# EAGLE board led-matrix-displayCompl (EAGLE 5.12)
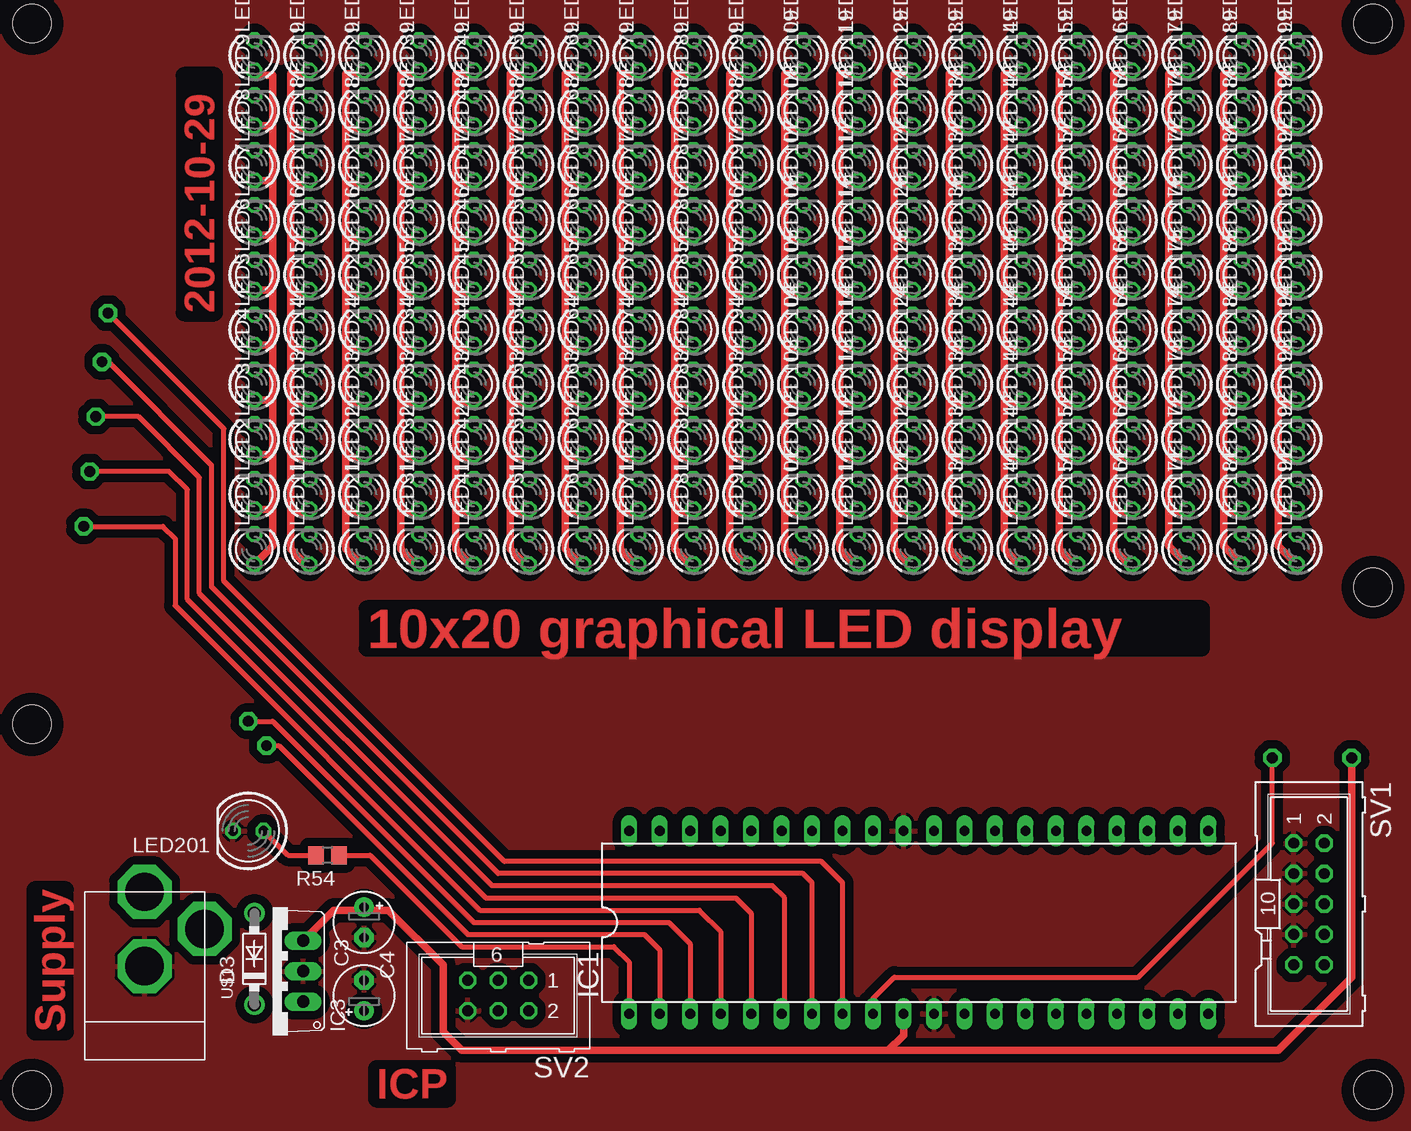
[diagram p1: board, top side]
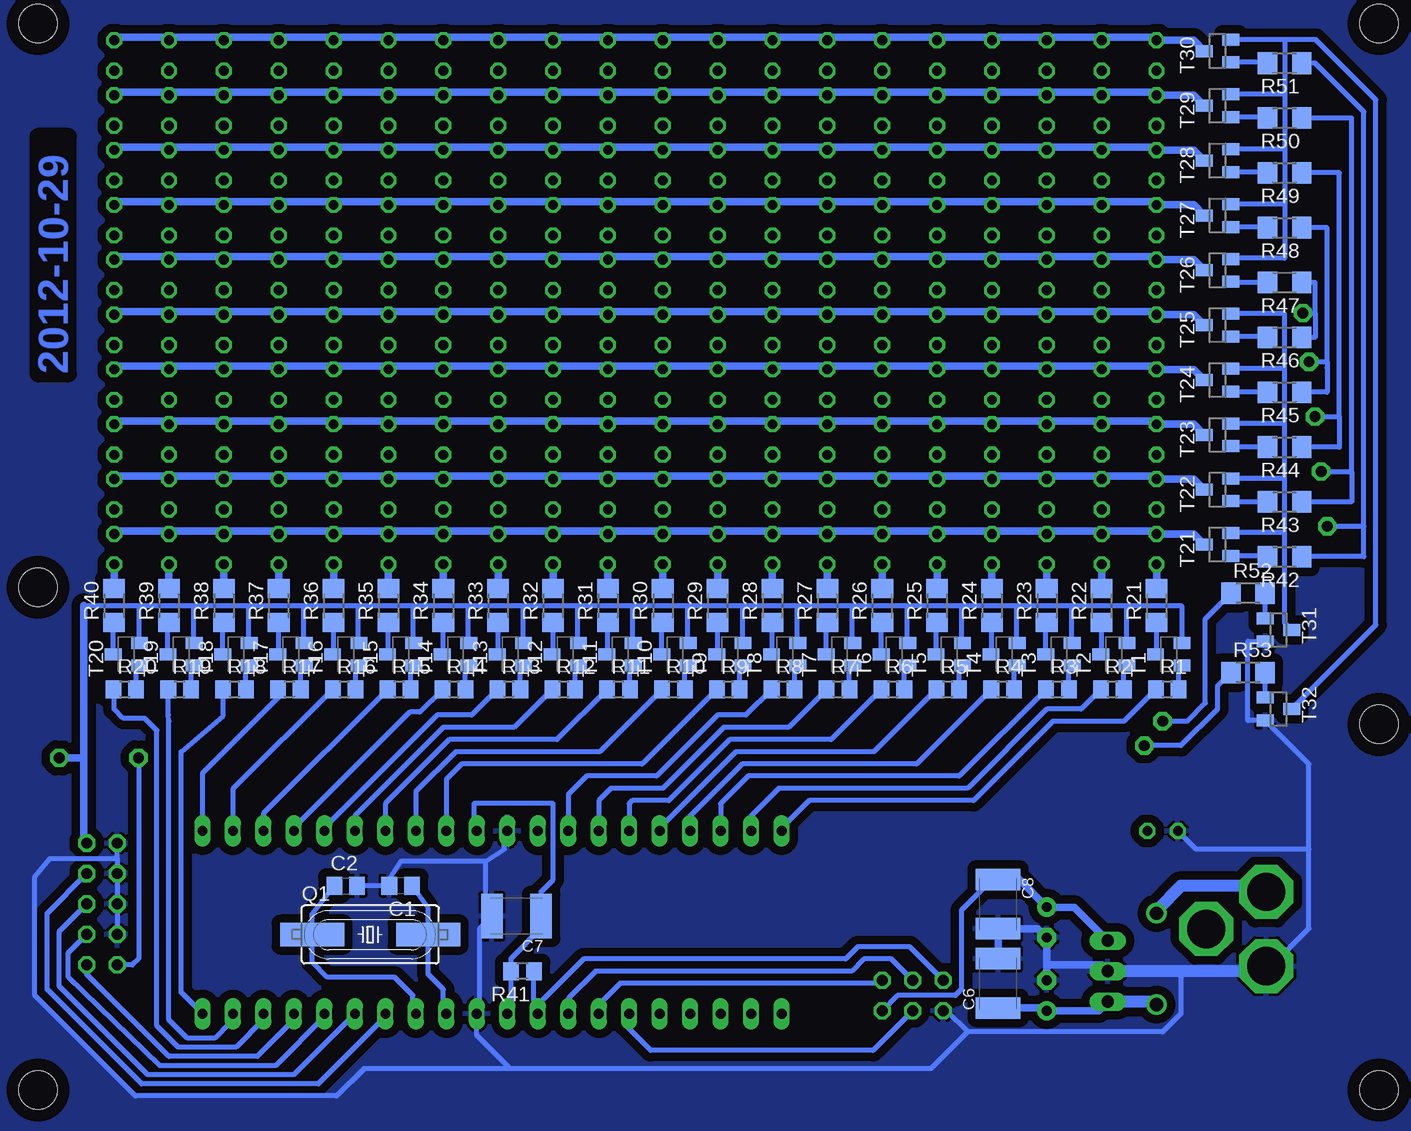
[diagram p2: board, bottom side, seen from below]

No outline drawn. Coordinates in mm, seen from the top.
Copper layers (1*16): Top 0.035mm / dielectric 1.5mm / Bottom 0.035mm
Design rules "default *": minimum track width 16mil, minimum drill 24mil, track to track 12mil, track to pad 12mil, pad to pad 12mil, via to via 8mil, smd to smd 8mil, copper to edge 40mil, drill to drill 8mil, minimum pad ring 10mil, minimum via ring 8mil, stop-mask expansion 4mil, vias tented up to drill 0mil, thermal gap 10mil
Holes 3.2 mm at 105.41,-6.35 105.41,82.55 -6.35,82.55 -6.35,24.13 -6.35,-6.35 105.41,35.56

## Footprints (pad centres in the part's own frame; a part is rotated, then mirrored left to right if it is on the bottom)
C0805 = smd 1.3 x 1.5: 1 -0.95,0; 2 0.95,0
E2,5-5 = drill 0.813 pad 1.6 round: + -1.27,0 | drill 0.813 pad 1.6 octagon: - 1.27,0
C1812K = smd 1.8 x 3.7: 1 -2.05,0; 2 2.05,0
DO41-7.6 = drill 1.1 pad 1.7 round: A 3.81,0; C -3.81,0
DIL40 = drill 0.813 long: 1 -24.13,-7.62; 2 -21.59,-7.62; 3 -19.05,-7.62; 4 -16.51,-7.62; 5 -13.97,-7.62; 6 -11.43,-7.62; 7 -8.89,-7.62; 8 -6.35,-7.62; 9 -3.81,-7.62; 10 -1.27,-7.62; 11 1.27,-7.62; 12 3.81,-7.62; 13 6.35,-7.62; 14 8.89,-7.62; 15 11.43,-7.62; 16 13.97,-7.62; 17 16.51,-7.62; 18 19.05,-7.62; 19 21.59,-7.62; 20 24.13,-7.62; 21 24.13,7.62; 22 21.59,7.62; 23 19.05,7.62; 24 16.51,7.62; 25 13.97,7.62; 26 11.43,7.62; 27 8.89,7.62; 28 6.35,7.62; 29 3.81,7.62; 30 1.27,7.62; 31 -1.27,7.62; 32 -3.81,7.62; 33 -6.35,7.62; 34 -8.89,7.62; 35 -11.43,7.62; 36 -13.97,7.62; 37 -16.51,7.62; 38 -19.05,7.62; 39 -21.59,7.62; 40 -24.13,7.62
TO220V = drill 1.016 long: 1 -2.54,-2.54; 2 0,-2.54; 3 2.54,-2.54
LED3MM = drill 0.813 octagon: A -1.27,0; K 1.27,0
LED5MM = drill 0.813 octagon: A -1.27,0; K 1.27,0
HC49UP = smd 5.334 x 1.93: 1 -4.826,0; 2 4.826,0
R0805 = smd 1.3 x 1.5: 1 -0.95,0; 2 0.95,0
R1206 = smd 1.6 x 1.803: 1 -1.422,0; 2 1.422,0
ML10 = drill 0.914 octagon: 1 -5.08,-1.27; 2 -5.08,1.27; 3 -2.54,-1.27; 4 -2.54,1.27; 5 0,-1.27; 6 0,1.27; 7 2.54,-1.27; 8 2.54,1.27; 9 5.08,-1.27; 10 5.08,1.27
ML6 = drill 0.914 octagon: 1 -2.54,-1.27; 2 -2.54,1.27; 3 0,-1.27; 4 0,1.27; 5 2.54,-1.27; 6 2.54,1.27
SOT23-BEC = smd 1 x 1.4: B -0.95,-1.1; C 0,1.1; E 0.95,-1.1
SOT23 = smd 1 x 1.4: 1 -0.95,-1.1; 2 0.95,-1.1; 3 0,1.1
HOHLBUCHSE = drill 3.2 pad 4.5 octagon: I 0,0; O 6.2,0; O2 3.1,5

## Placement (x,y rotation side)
C1  [C0805]  75.18,10.67 180 bottom
C2  [C0805]  79.76,10.67 0 bottom
C3  [E2,5-5]  21.34,1.52 90 top
C4  [E2,5-5]  21.34,7.62 270 top
C6  [C1812K]  25.4,2.54 90 bottom
C7  [C1812K]  65.53,8.13 180 bottom
C8  [C1812K]  25.4,9.14 270 bottom
D3  1N5817-B  [DO41-7.6]  12.19,4.57 90 top
IC1  MEGA32-P  [DIL40]  67.56,7.62 0 top
IC3  7805TV  [TO220V]  13.72,3.56 90 top
LED1  [LED3MM]  12.19,38.73 90 top
LED2  [LED3MM]  12.19,43.31 90 top
LED3  [LED3MM]  12.19,47.88 90 top
LED4  [LED3MM]  12.19,52.45 90 top
LED5  [LED3MM]  12.19,57.02 90 top
LED6  [LED3MM]  12.19,61.59 90 top
LED7  [LED3MM]  12.19,66.17 90 top
LED8  [LED3MM]  12.19,70.74 90 top
LED9  [LED3MM]  12.19,75.31 90 top
LED10  [LED3MM]  12.19,79.88 90 top
LED11  [LED3MM]  16.76,38.73 90 top
LED12  [LED3MM]  16.76,43.31 90 top
LED13  [LED3MM]  16.76,47.88 90 top
LED14  [LED3MM]  16.76,52.45 90 top
LED15  [LED3MM]  16.76,57.02 90 top
LED16  [LED3MM]  16.76,61.59 90 top
LED17  [LED3MM]  16.76,66.17 90 top
LED18  [LED3MM]  16.76,70.74 90 top
LED19  [LED3MM]  16.76,75.31 90 top
LED20  [LED3MM]  16.76,79.88 90 top
LED21  [LED3MM]  21.34,38.73 90 top
LED22  [LED3MM]  21.34,43.31 90 top
LED23  [LED3MM]  21.34,47.88 90 top
LED24  [LED3MM]  21.34,52.45 90 top
LED25  [LED3MM]  21.34,57.02 90 top
LED26  [LED3MM]  21.34,61.59 90 top
LED27  [LED3MM]  21.34,66.17 90 top
LED28  [LED3MM]  21.34,70.74 90 top
LED29  [LED3MM]  21.34,75.31 90 top
LED30  [LED3MM]  21.34,79.88 90 top
LED31  [LED3MM]  25.91,38.73 90 top
LED32  [LED3MM]  25.91,43.31 90 top
LED33  [LED3MM]  25.91,47.88 90 top
LED34  [LED3MM]  25.91,52.45 90 top
LED35  [LED3MM]  25.91,57.02 90 top
LED36  [LED3MM]  25.91,61.59 90 top
LED37  [LED3MM]  25.91,66.17 90 top
LED38  [LED3MM]  25.91,70.74 90 top
LED39  [LED3MM]  25.91,75.31 90 top
LED40  [LED3MM]  25.91,79.88 90 top
LED41  [LED3MM]  30.48,38.73 90 top
LED42  [LED3MM]  30.48,43.31 90 top
LED43  [LED3MM]  30.48,47.88 90 top
LED44  [LED3MM]  30.48,52.45 90 top
LED45  [LED3MM]  30.48,57.02 90 top
LED46  [LED3MM]  30.48,61.59 90 top
LED47  [LED3MM]  30.48,66.17 90 top
LED48  [LED3MM]  30.48,70.74 90 top
LED49  [LED3MM]  30.48,75.31 90 top
LED50  [LED3MM]  30.48,79.88 90 top
LED51  [LED3MM]  35.05,38.73 90 top
LED52  [LED3MM]  35.05,43.31 90 top
LED53  [LED3MM]  35.05,47.88 90 top
LED54  [LED3MM]  35.05,52.45 90 top
LED55  [LED3MM]  35.05,57.02 90 top
LED56  [LED3MM]  35.05,61.59 90 top
LED57  [LED3MM]  35.05,66.17 90 top
LED58  [LED3MM]  35.05,70.74 90 top
LED59  [LED3MM]  35.05,75.31 90 top
LED60  [LED3MM]  35.05,79.88 90 top
LED61  [LED3MM]  39.62,38.73 90 top
LED62  [LED3MM]  39.62,43.31 90 top
LED63  [LED3MM]  39.62,47.88 90 top
LED64  [LED3MM]  39.62,52.45 90 top
LED65  [LED3MM]  39.62,57.02 90 top
LED66  [LED3MM]  39.62,61.59 90 top
LED67  [LED3MM]  39.62,66.17 90 top
LED68  [LED3MM]  39.62,70.74 90 top
LED69  [LED3MM]  39.62,75.31 90 top
LED70  [LED3MM]  39.62,79.88 90 top
LED71  [LED3MM]  44.2,38.73 90 top
LED72  [LED3MM]  44.2,43.31 90 top
LED73  [LED3MM]  44.2,47.88 90 top
LED74  [LED3MM]  44.2,52.45 90 top
LED75  [LED3MM]  44.2,57.02 90 top
LED76  [LED3MM]  44.2,61.59 90 top
LED77  [LED3MM]  44.2,66.17 90 top
LED78  [LED3MM]  44.2,70.74 90 top
LED79  [LED3MM]  44.2,75.31 90 top
LED80  [LED3MM]  44.2,79.88 90 top
LED81  [LED3MM]  48.77,38.73 90 top
LED82  [LED3MM]  48.77,43.31 90 top
LED83  [LED3MM]  48.77,47.88 90 top
LED84  [LED3MM]  48.77,52.45 90 top
LED85  [LED3MM]  48.77,57.02 90 top
LED86  [LED3MM]  48.77,61.59 90 top
LED87  [LED3MM]  48.77,66.17 90 top
LED88  [LED3MM]  48.77,70.74 90 top
LED89  [LED3MM]  48.77,75.31 90 top
LED90  [LED3MM]  48.77,79.88 90 top
LED91  [LED3MM]  53.34,38.73 90 top
LED92  [LED3MM]  53.34,43.31 90 top
LED93  [LED3MM]  53.34,47.88 90 top
LED94  [LED3MM]  53.34,52.45 90 top
LED95  [LED3MM]  53.34,57.02 90 top
LED96  [LED3MM]  53.34,61.59 90 top
LED97  [LED3MM]  53.34,66.17 90 top
LED98  [LED3MM]  53.34,70.74 90 top
LED99  [LED3MM]  53.34,75.31 90 top
LED100  [LED3MM]  53.34,79.88 90 top
LED101  [LED3MM]  57.91,38.73 90 top
LED102  [LED3MM]  57.91,43.31 90 top
LED103  [LED3MM]  57.91,47.88 90 top
LED104  [LED3MM]  57.91,52.45 90 top
LED105  [LED3MM]  57.91,57.02 90 top
LED106  [LED3MM]  57.91,61.59 90 top
LED107  [LED3MM]  57.91,66.17 90 top
LED108  [LED3MM]  57.91,70.74 90 top
LED109  [LED3MM]  57.91,75.31 90 top
LED110  [LED3MM]  57.91,79.88 90 top
LED111  [LED3MM]  62.48,38.73 90 top
LED112  [LED3MM]  62.48,43.31 90 top
LED113  [LED3MM]  62.48,47.88 90 top
LED114  [LED3MM]  62.48,52.45 90 top
LED115  [LED3MM]  62.48,57.02 90 top
LED116  [LED3MM]  62.48,61.59 90 top
LED117  [LED3MM]  62.48,66.17 90 top
LED118  [LED3MM]  62.48,70.74 90 top
LED119  [LED3MM]  62.48,75.31 90 top
LED120  [LED3MM]  62.48,79.88 90 top
LED121  [LED3MM]  67.06,38.73 90 top
LED122  [LED3MM]  67.06,43.31 90 top
LED123  [LED3MM]  67.06,47.88 90 top
LED124  [LED3MM]  67.06,52.45 90 top
LED125  [LED3MM]  67.06,57.02 90 top
LED126  [LED3MM]  67.06,61.59 90 top
LED127  [LED3MM]  67.06,66.17 90 top
LED128  [LED3MM]  67.06,70.74 90 top
LED129  [LED3MM]  67.06,75.31 90 top
LED130  [LED3MM]  67.06,79.88 90 top
LED131  [LED3MM]  71.63,38.73 90 top
LED132  [LED3MM]  71.63,43.31 90 top
LED133  [LED3MM]  71.63,47.88 90 top
LED134  [LED3MM]  71.63,52.45 90 top
LED135  [LED3MM]  71.63,57.02 90 top
LED136  [LED3MM]  71.63,61.59 90 top
LED137  [LED3MM]  71.63,66.17 90 top
LED138  [LED3MM]  71.63,70.74 90 top
LED139  [LED3MM]  71.63,75.31 90 top
LED140  [LED3MM]  71.63,79.88 90 top
LED141  [LED3MM]  76.2,38.73 90 top
LED142  [LED3MM]  76.2,43.31 90 top
LED143  [LED3MM]  76.2,47.88 90 top
LED144  [LED3MM]  76.2,52.45 90 top
LED145  [LED3MM]  76.2,57.02 90 top
LED146  [LED3MM]  76.2,61.59 90 top
LED147  [LED3MM]  76.2,66.17 90 top
LED148  [LED3MM]  76.2,70.74 90 top
LED149  [LED3MM]  76.2,75.31 90 top
LED150  [LED3MM]  76.2,79.88 90 top
LED151  [LED3MM]  80.77,38.73 90 top
LED152  [LED3MM]  80.77,43.31 90 top
LED153  [LED3MM]  80.77,47.88 90 top
LED154  [LED3MM]  80.77,52.45 90 top
LED155  [LED3MM]  80.77,57.02 90 top
LED156  [LED3MM]  80.77,61.59 90 top
LED157  [LED3MM]  80.77,66.17 90 top
LED158  [LED3MM]  80.77,70.74 90 top
LED159  [LED3MM]  80.77,75.31 90 top
LED160  [LED3MM]  80.77,79.88 90 top
LED161  [LED3MM]  85.34,38.73 90 top
LED162  [LED3MM]  85.34,43.31 90 top
LED163  [LED3MM]  85.34,47.88 90 top
LED164  [LED3MM]  85.34,52.45 90 top
LED165  [LED3MM]  85.34,57.02 90 top
LED166  [LED3MM]  85.34,61.59 90 top
LED167  [LED3MM]  85.34,66.17 90 top
LED168  [LED3MM]  85.34,70.74 90 top
LED169  [LED3MM]  85.34,75.31 90 top
LED170  [LED3MM]  85.34,79.88 90 top
LED171  [LED3MM]  89.92,38.73 90 top
LED172  [LED3MM]  89.92,43.31 90 top
LED173  [LED3MM]  89.92,47.88 90 top
LED174  [LED3MM]  89.92,52.45 90 top
LED175  [LED3MM]  89.92,57.02 90 top
LED176  [LED3MM]  89.92,61.59 90 top
LED177  [LED3MM]  89.92,66.17 90 top
LED178  [LED3MM]  89.92,70.74 90 top
LED179  [LED3MM]  89.92,75.31 90 top
LED180  [LED3MM]  89.92,79.88 90 top
LED181  [LED3MM]  94.49,38.73 90 top
LED182  [LED3MM]  94.49,43.31 90 top
LED183  [LED3MM]  94.49,47.88 90 top
LED184  [LED3MM]  94.49,52.45 90 top
LED185  [LED3MM]  94.49,57.02 90 top
LED186  [LED3MM]  94.49,61.59 90 top
LED187  [LED3MM]  94.49,66.17 90 top
LED188  [LED3MM]  94.49,70.74 90 top
LED189  [LED3MM]  94.49,75.31 90 top
LED190  [LED3MM]  94.49,79.88 90 top
LED191  [LED3MM]  99.06,38.73 90 top
LED192  [LED3MM]  99.06,43.31 90 top
LED193  [LED3MM]  99.06,47.88 90 top
LED194  [LED3MM]  99.06,52.45 90 top
LED195  [LED3MM]  99.06,57.02 90 top
LED196  [LED3MM]  99.06,61.59 90 top
LED197  [LED3MM]  99.06,66.17 90 top
LED198  [LED3MM]  99.06,70.74 90 top
LED199  [LED3MM]  99.06,75.31 90 top
LED200  [LED3MM]  99.06,79.88 90 top
LED201  [LED5MM]  11.68,15.24 180 top
Q1  [HC49UP]  77.72,6.6 0 bottom
R1  10k  [R0805]  11.3,27.05 0 bottom
R2  10k  [R0805]  15.88,27.05 0 bottom
R3  10k  [R0805]  20.45,27.05 0 bottom
R4  10k  [R0805]  25.02,27.05 0 bottom
R5  10k  [R0805]  29.59,27.05 0 bottom
R6  10k  [R0805]  34.16,27.05 0 bottom
R7  10k  [R0805]  38.73,27.05 0 bottom
R8  10k  [R0805]  43.31,27.05 0 bottom
R9  10k  [R0805]  47.88,27.05 0 bottom
R10  10k  [R0805]  52.45,27.05 0 bottom
R11  10k  [R0805]  57.02,27.05 0 bottom
R12  10k  [R0805]  61.59,27.05 0 bottom
R13  10k  [R0805]  66.17,27.05 0 bottom
R14  10k  [R0805]  70.74,27.05 0 bottom
R15  10k  [R0805]  75.31,27.05 0 bottom
R16  10k  [R0805]  79.88,27.05 0 bottom
R17  10k  [R0805]  84.45,27.05 0 bottom
R18  10k  [R0805]  89.03,27.05 0 bottom
R19  10k  [R0805]  93.6,27.05 0 bottom
R20  10k  [R0805]  98.17,27.05 0 bottom
R21  [R1206]  12.19,34.04 90 bottom
R22  [R1206]  16.76,34.04 90 bottom
R23  [R1206]  21.34,34.04 90 bottom
R24  [R1206]  25.91,34.04 90 bottom
R25  [R1206]  30.48,34.04 90 bottom
R26  [R1206]  35.05,34.04 90 bottom
R27  [R1206]  39.62,34.04 90 bottom
R28  [R1206]  44.2,34.04 90 bottom
R29  [R1206]  48.77,34.04 90 bottom
R30  [R1206]  53.34,34.04 90 bottom
R31  [R1206]  57.91,34.04 90 bottom
R32  [R1206]  62.48,34.04 90 bottom
R33  [R1206]  67.06,34.04 90 bottom
R34  [R1206]  71.63,34.04 90 bottom
R35  [R1206]  76.2,34.04 90 bottom
R36  [R1206]  80.77,34.04 90 bottom
R37  [R1206]  85.34,34.04 90 bottom
R38  [R1206]  89.92,34.04 90 bottom
R39  [R1206]  94.49,34.04 90 bottom
R40  [R1206]  99.06,34.04 90 bottom
R41  [R0805]  65.02,3.56 180 bottom
R42  4k7  [R1206]  1.52,38.1 180 bottom
R43  4k7  [R1206]  1.52,42.67 180 bottom
R44  4k7  [R1206]  1.52,47.24 180 bottom
R45  4k7  [R1206]  1.52,51.82 180 bottom
R46  4k7  [R1206]  1.52,56.39 180 bottom
R47  4k7  [R1206]  1.52,60.96 180 bottom
R48  4k7  [R1206]  1.52,65.53 180 bottom
R49  4k7  [R1206]  1.52,70.1 180 bottom
R50  4k7  [R1206]  1.52,74.68 180 bottom
R51  4k7  [R1206]  1.52,79.25 180 bottom
R52  4k7  [R1206]  4.57,35.05 0 bottom
R53  4k7  [R1206]  4.57,28.45 0 bottom
R54  [R0805]  18.29,13.21 180 top
SV1  [ML10]  100.08,9.14 270 top
SV2  [ML6]  32.51,1.52 180 top
T1  [SOT23-BEC]  11.18,29.97 90 bottom
T2  [SOT23-BEC]  15.75,29.97 90 bottom
T3  [SOT23-BEC]  20.32,29.97 90 bottom
T4  [SOT23-BEC]  24.89,29.97 90 bottom
T5  [SOT23-BEC]  29.46,29.97 90 bottom
T6  [SOT23-BEC]  34.04,29.97 90 bottom
T7  [SOT23-BEC]  38.61,29.97 90 bottom
T8  [SOT23-BEC]  43.18,29.97 90 bottom
T9  [SOT23-BEC]  47.75,29.97 90 bottom
T10  [SOT23-BEC]  52.32,29.97 90 bottom
T11  [SOT23-BEC]  56.9,29.97 90 bottom
T12  [SOT23-BEC]  61.47,29.97 90 bottom
T13  [SOT23-BEC]  66.04,29.97 90 bottom
T14  [SOT23-BEC]  70.61,29.97 90 bottom
T15  [SOT23-BEC]  75.18,29.97 90 bottom
T16  [SOT23-BEC]  79.76,29.97 90 bottom
T17  [SOT23-BEC]  84.33,29.97 90 bottom
T18  [SOT23-BEC]  88.9,29.97 90 bottom
T19  [SOT23-BEC]  93.47,29.97 90 bottom
T20  [SOT23-BEC]  98.04,29.97 90 bottom
T21  BC818  [SOT23]  7.11,39.12 90 bottom
T22  BC818  [SOT23]  7.11,43.69 90 bottom
T23  BC818  [SOT23]  7.11,48.26 90 bottom
T24  BC818  [SOT23]  7.11,52.83 90 bottom
T25  BC818  [SOT23]  7.11,57.4 90 bottom
T26  BC818  [SOT23]  7.11,61.98 90 bottom
T27  BC818  [SOT23]  7.11,66.55 90 bottom
T28  BC818  [SOT23]  7.11,71.12 90 bottom
T29  BC818  [SOT23]  7.11,75.69 90 bottom
T30  BC818  [SOT23]  7.11,80.26 90 bottom
T31  BC818  [SOT23]  2.03,32 270 bottom
T32  BC818  [SOT23]  2.03,25.4 270 bottom
U$1  HOHLBUCHSE  [HOHLBUCHSE]  3.05,10.16 270 top

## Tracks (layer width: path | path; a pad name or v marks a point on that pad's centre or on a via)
+5V  (via drill 0.9 pad 1.52)
  Top 0.61: IC3.3 18.8,8.64 23.37,8.64 27.94,4.06 27.94,-1.52 29.46,-3.05 65.02,-3.05 | 65.02,-3.05 66.29,-1.78 IC1.10 | 65.02,-3.05 97.54,-3.05 103.63,3.05 v103.63,21.34
  Bottom 0.406: IC1.10 65.97,0.32 R41.2 65.97,4.62 63.5,7.11 63.5,8.13 C7.1 63.48,10.18 62.48,11.18 62.48,17.53 69.09,17.53 69.09,15.49 IC1.30 | 101.6,14.48 SV1.2 | 14.73,34.04 10.16,34.04 10.08,33.95 T1.E | 19.3,34.04 14.73,34.04 | 23.88,34.04 19.3,34.04 | 28.45,34.04 23.88,34.04 | 33.02,34.04 28.45,34.04 | 37.59,34.04 33.02,34.04 | 42.16,34.04 37.59,34.04 | 46.74,34.04 42.16,34.04 | 51.31,34.04 46.74,34.04 | 55.88,34.04 51.31,34.04 | 60.45,34.04 55.88,34.04 | 65.02,34.04 60.45,34.04 | 69.6,34.04 65.02,34.04 | 74.17,34.04 69.6,34.04 | 78.74,34.04 74.17,34.04 | 83.31,34.04 78.74,34.04 | 87.88,34.04 83.31,34.04 | 92.46,34.04 87.88,34.04 | 97.03,34.04 92.46,34.04 | 101.6,34.04 97.03,34.04 | T2.E 14.73,31.01 14.73,34.04 | T3.E 19.3,31.01 19.3,34.04 | T4.E 23.88,31.01 23.88,34.04 | T5.E 28.45,31.01 28.45,34.04 | T6.E 33.02,31.01 33.02,34.04 | T7.E 37.59,31.01 37.59,34.04 | T8.E 42.16,31.01 42.16,34.04 | T9.E 46.74,31.01 46.74,34.04 | T10.E 51.31,31.01 51.31,34.04 | T12.E 60.45,31.01 60.45,34.04 | T11.E 55.88,31.01 55.88,34.04 | T13.E 65.02,31.01 65.02,34.04 | T14.E 69.6,31.01 69.6,34.04 | T15.E 74.17,31.01 74.17,34.04 | T16.E 78.74,31.01 78.74,34.04 | T17.E 83.31,31.01 83.31,34.04 | T18.E 87.88,31.01 87.88,34.04 | T19.E 92.46,31.01 92.46,34.04 | T20.E 97.03,31.01 97.03,34.04 | SV2.2 33.78,1.52 28.96,1.52 28.45,2.03 28.45,8.64 25.89,11.19 C8.1
  Bottom 0.61: IC3.3 19.05,8.89 C4.+ 23.64,11.19 C8.1 | 101.6,21.34 101.6,34.04 | 101.6,21.34 101.6,14.48 | v103.63,21.34 101.6,21.34
GND
  Bottom 0.406: C2.2 C1.2 76.13,11.24 75.18,12.7 68.07,12.7 | IC1.31 66.55,14.99 66.55,13.72 68.07,12.7 | 68.07,12.7 68.07,8.62 C7.2 67.58,8.11 68.58,7.11 68.58,0.25 IC1.11 68.83,-1.78 66.04,-4.57 | SV1.7 SV1.5 SV1.3 98.81,12.94 | 98.81,12.94 SV1.1 | 9.65,3.56 10.16,3.05 10.16,0 11.68,-1.52 27.94,-1.52 | 27.94,-1.52 29.72,0.25 SV2.6 | T31.2 4.57,31.05 4.57,24.45 T32.2 -0.51,20.81 -0.51,13.72 | -0.51,13.72 -0.51,7.11 2.64,3.96 U$1.O | LED201.K 8.89,13.72 -0.51,13.72 | 27.94,-1.52 30.99,-4.57 66.04,-4.57 | 98.81,12.94 98.83,12.95 104.39,12.95 105.66,11.43 105.66,1.52 97.28,-6.86 80.52,-6.86 78.23,-4.57 66.04,-4.57
  Bottom 0.61: C6.2 C8.2 22.08,7.09 C4.- 21.34,4.06 | 21.34,4.06 C3.- | IC3.2 16.76,4.06 21.34,4.06
  Bottom 1.016: U$1.O 3.45,3.56 9.65,3.56 IC3.2
  pour Top (isolate 0.711): 109.22,-10.16 109.22,86.36 -10.16,86.36 -10.16,-10.16
  pour Bottom (isolate 0.711): 109.22,-10.16 109.22,86.36 -10.16,86.36 -10.16,-10.16
N$1
  Top 0.61: LED1.A 13.72,38.99 13.72,42.04 | 13.72,69.47 13.72,74.04 | LED10.A arc90 12.57,78.23 13.72,78.23 13.72,74.04 | 13.72,74.04 LED9.A | 13.72,69.47 LED8.A | 13.72,64.9 LED7.A | 13.72,64.9 13.72,69.47 | 13.72,60.33 LED6.A | 13.72,60.33 13.72,64.9 | 13.72,55.75 LED5.A | 13.72,55.75 13.72,60.33 | 13.72,51.18 LED4.A | 13.72,51.18 13.72,55.75 | 13.72,46.61 LED3.A | 13.72,46.61 13.72,51.18 | 13.72,42.04 LED2.A | 13.72,42.04 13.72,46.61
  Bottom 0.61: R21.2 LED1.A
N$2
  Top 0.61: 16.76,37.21 15.24,38.73 15.24,41.78 | 15.24,41.78 16.76,41.78 LED12.A | 15.24,46.35 16.76,46.35 LED13.A | 15.24,41.78 15.24,46.35 | 15.24,50.93 16.76,50.93 LED14.A | 15.24,46.35 15.24,50.93 | 15.24,55.5 16.76,55.5 LED15.A | 15.24,50.93 15.24,55.5 | 15.24,60.07 16.76,60.07 LED16.A | 15.24,55.5 15.24,60.07 | 15.24,64.64 16.76,64.64 LED17.A | 15.24,60.07 15.24,64.64 | 15.24,69.22 16.76,69.22 LED18.A | 15.24,64.64 15.24,69.22 | 15.24,73.79 16.76,73.79 LED19.A | 15.24,69.22 15.24,73.79 | 15.24,73.79 15.24,78.36 16.76,78.36 LED20.A | 16.76,37.21 16.51,37.21 | LED11.A 16.76,37.21
  Bottom 0.61: R22.2 LED11.A
N$3
  Top 0.61: 21.34,37.21 19.81,38.73 19.81,41.78 | 19.81,41.78 21.34,41.78 LED22.A | 19.81,46.35 21.34,46.35 LED23.A | 19.81,41.78 19.81,46.35 | 19.81,50.93 21.34,50.93 LED24.A | 19.81,46.35 19.81,50.93 | 19.81,55.5 21.34,55.5 LED25.A | 19.81,50.93 19.81,55.5 | 19.81,60.07 21.34,60.07 LED26.A | 19.81,55.5 19.81,60.07 | 19.81,64.64 21.34,64.64 LED27.A | 19.81,60.07 19.81,64.64 | 19.81,69.22 21.34,69.22 LED28.A | 19.81,64.64 19.81,69.22 | 19.81,73.79 21.34,73.79 LED29.A | 19.81,69.22 19.81,73.79 | 19.81,73.79 19.81,78.36 21.34,78.36 LED30.A | 21.34,37.21 21.08,37.21 | LED21.A 21.34,37.21
  Bottom 0.61: R23.2 LED21.A
N$4
  Top 0.61: 24.38,41.78 24.38,38.73 25.65,37.47 LED31.A | 24.38,41.78 25.91,41.78 LED32.A | 24.38,46.35 25.91,46.35 LED33.A | 24.38,41.78 24.38,46.35 | 24.38,50.93 25.91,50.93 LED34.A | 24.38,46.35 24.38,50.93 | 24.38,55.5 25.91,55.5 LED35.A | 24.38,50.93 24.38,55.5 | 24.38,60.07 25.91,60.07 LED36.A | 24.38,55.5 24.38,60.07 | 24.38,64.64 25.91,64.64 LED37.A | 24.38,60.07 24.38,64.64 | 24.38,69.22 25.91,69.22 LED38.A | 24.38,64.64 24.38,69.22 | 24.38,73.79 25.91,73.79 LED39.A | 24.38,69.22 24.38,73.79 | 24.38,73.79 24.38,78.36 25.91,78.36 LED40.A
  Bottom 0.61: R24.2 LED31.A
N$5
  Top 0.61: 30.23,37.47 30.48,37.21 30.23,37.21 | 28.96,41.78 28.96,38.73 30.23,37.47 | 28.96,41.78 30.48,41.78 LED42.A | 28.96,46.35 30.48,46.35 LED43.A | 28.96,41.78 28.96,46.35 | 28.96,50.93 30.48,50.93 LED44.A | 28.96,46.35 28.96,50.93 | 28.96,55.5 30.48,55.5 LED45.A | 28.96,50.93 28.96,55.5 | 28.96,60.07 30.48,60.07 LED46.A | 28.96,55.5 28.96,60.07 | 28.96,64.64 30.48,64.64 LED47.A | 28.96,60.07 28.96,64.64 | 28.96,69.22 30.48,69.22 LED48.A | 28.96,64.64 28.96,69.22 | 28.96,73.79 30.48,73.79 LED49.A | 28.96,69.22 28.96,73.79 | 28.96,73.79 28.96,78.36 30.48,78.36 LED50.A | LED41.A 30.23,37.47
  Bottom 0.61: R25.2 LED41.A
N$6
  Top 0.61: 35.05,37.21 33.53,38.73 33.53,41.78 | 33.53,41.78 35.05,41.78 LED52.A | 33.53,46.35 35.05,46.35 LED53.A | 33.53,41.78 33.53,46.35 | 33.53,50.93 35.05,50.93 LED54.A | 33.53,46.35 33.53,50.93 | 33.53,55.5 35.05,55.5 LED55.A | 33.53,50.93 33.53,55.5 | 33.53,60.07 35.05,60.07 LED56.A | 33.53,55.5 33.53,60.07 | 33.53,64.64 35.05,64.64 LED57.A | 33.53,60.07 33.53,64.64 | 33.53,69.22 35.05,69.22 LED58.A | 33.53,64.64 33.53,69.22 | 33.53,73.79 35.05,73.79 LED59.A | 33.53,69.22 33.53,73.79 | 33.53,73.79 33.53,78.36 35.05,78.36 LED60.A | 35.05,37.21 34.8,37.21 | LED51.A 35.05,37.21
  Bottom 0.61: R26.2 LED51.A
N$7
  Top 0.61: 39.62,37.21 38.1,38.73 38.1,41.78 | 38.1,41.78 39.62,41.78 LED62.A | 38.1,46.35 39.62,46.35 LED63.A | 38.1,41.78 38.1,46.35 | 38.1,50.93 39.62,50.93 LED64.A | 38.1,46.35 38.1,50.93 | 38.1,55.5 39.62,55.5 LED65.A | 38.1,50.93 38.1,55.5 | 38.1,60.07 39.62,60.07 LED66.A | 38.1,55.5 38.1,60.07 | 38.1,64.64 39.62,64.64 LED67.A | 38.1,60.07 38.1,64.64 | 38.1,69.22 39.62,69.22 LED68.A | 38.1,64.64 38.1,69.22 | 38.1,73.79 39.62,73.79 LED69.A | 38.1,69.22 38.1,73.79 | 38.1,73.79 38.1,78.36 39.62,78.36 LED70.A | 39.62,37.21 39.37,37.21 | LED61.A 39.62,37.21
  Bottom 0.61: R27.2 LED61.A
N$8
  Top 0.61: 44.2,37.21 42.67,38.73 42.67,41.78 | 42.67,41.78 44.2,41.78 LED72.A | 42.67,46.35 44.2,46.35 LED73.A | 42.67,41.78 42.67,46.35 | 42.67,50.93 44.2,50.93 LED74.A | 42.67,46.35 42.67,50.93 | 42.67,55.5 44.2,55.5 LED75.A | 42.67,50.93 42.67,55.5 | 42.67,60.07 44.2,60.07 LED76.A | 42.67,55.5 42.67,60.07 | 42.67,64.64 44.2,64.64 LED77.A | 42.67,60.07 42.67,64.64 | 42.67,69.22 44.2,69.22 LED78.A | 42.67,64.64 42.67,69.22 | 42.67,73.79 44.2,73.79 LED79.A | 42.67,69.22 42.67,73.79 | 42.67,73.79 42.67,78.36 44.2,78.36 LED80.A | 44.2,37.21 43.94,37.21 | LED71.A 44.2,37.21
  Bottom 0.61: R28.2 LED71.A
N$9
  Top 0.61: 48.77,37.21 47.24,38.73 47.24,41.78 | 47.24,41.78 48.77,41.78 LED82.A | 47.24,46.35 48.77,46.35 LED83.A | 47.24,41.78 47.24,46.35 | 47.24,50.93 48.77,50.93 LED84.A | 47.24,46.35 47.24,50.93 | 47.24,55.5 48.77,55.5 LED85.A | 47.24,50.93 47.24,55.5 | 47.24,60.07 48.77,60.07 LED86.A | 47.24,55.5 47.24,60.07 | 47.24,64.64 48.77,64.64 LED87.A | 47.24,60.07 47.24,64.64 | 47.24,69.22 48.77,69.22 LED88.A | 47.24,64.64 47.24,69.22 | 47.24,73.79 48.77,73.79 LED89.A | 47.24,69.22 47.24,73.79 | 47.24,73.79 47.24,78.36 48.77,78.36 LED90.A | 48.77,37.21 48.51,37.21 | LED81.A 48.77,37.21
  Bottom 0.61: R29.2 LED81.A
N$10
  Top 0.61: 53.09,37.47 53.34,37.21 53.09,37.21 | 51.82,41.78 51.82,38.73 53.09,37.47 | 51.82,41.78 53.34,41.78 LED92.A | 51.82,46.35 53.34,46.35 LED93.A | 51.82,41.78 51.82,46.35 | 51.82,50.93 53.34,50.93 LED94.A | 51.82,46.35 51.82,50.93 | 51.82,55.5 53.34,55.5 LED95.A | 51.82,50.93 51.82,55.5 | 51.82,60.07 53.34,60.07 LED96.A | 51.82,55.5 51.82,60.07 | 51.82,64.64 53.34,64.64 LED97.A | 51.82,60.07 51.82,64.64 | 51.82,69.22 53.34,69.22 LED98.A | 51.82,64.64 51.82,69.22 | 51.82,73.79 53.34,73.79 LED99.A | 51.82,69.22 51.82,73.79 | 51.82,73.79 51.82,78.36 53.34,78.36 LED100.A | LED91.A 53.09,37.47
  Bottom 0.61: R30.2 LED91.A
N$11
  Top 0.61: 57.91,37.21 56.39,38.73 56.39,41.78 | 56.39,41.78 57.91,41.78 LED102.A | 56.39,46.35 57.91,46.35 LED103.A | 56.39,41.78 56.39,46.35 | 56.39,50.93 57.91,50.93 LED104.A | 56.39,46.35 56.39,50.93 | 56.39,55.5 57.91,55.5 LED105.A | 56.39,50.93 56.39,55.5 | 56.39,60.07 57.91,60.07 LED106.A | 56.39,55.5 56.39,60.07 | 56.39,64.64 57.91,64.64 LED107.A | 56.39,60.07 56.39,64.64 | 56.39,69.22 57.91,69.22 LED108.A | 56.39,64.64 56.39,69.22 | 56.39,73.79 57.91,73.79 LED109.A | 56.39,69.22 56.39,73.79 | 56.39,73.79 56.39,78.36 57.91,78.36 LED110.A | 57.91,37.21 57.66,37.21 | LED101.A 57.91,37.21
  Bottom 0.61: R31.2 LED101.A
N$12
  Top 0.61: 62.48,37.21 60.96,38.73 60.96,41.78 | 60.96,41.78 62.48,41.78 LED112.A | 60.96,46.35 62.48,46.35 LED113.A | 60.96,41.78 60.96,46.35 | 60.96,50.93 62.48,50.93 LED114.A | 60.96,46.35 60.96,50.93 | 60.96,55.5 62.48,55.5 LED115.A | 60.96,50.93 60.96,55.5 | 60.96,60.07 62.48,60.07 LED116.A | 60.96,55.5 60.96,60.07 | 60.96,64.64 62.48,64.64 LED117.A | 60.96,60.07 60.96,64.64 | 60.96,69.22 62.48,69.22 LED118.A | 60.96,64.64 60.96,69.22 | 60.96,73.79 62.48,73.79 LED119.A | 60.96,69.22 60.96,73.79 | 60.96,73.79 60.96,78.36 62.48,78.36 LED120.A | 62.48,37.21 62.23,37.21 | LED111.A 62.48,37.21
  Bottom 0.61: R32.2 LED111.A
N$13
  Top 0.61: 66.8,37.47 67.06,37.21 66.8,37.21 | 65.53,41.78 65.53,38.73 66.8,37.47 | 65.53,41.78 67.06,41.78 LED122.A | 65.53,46.35 67.06,46.35 LED123.A | 65.53,41.78 65.53,46.35 | 65.53,50.93 67.06,50.93 LED124.A | 65.53,46.35 65.53,50.93 | 65.53,55.5 67.06,55.5 LED125.A | 65.53,50.93 65.53,55.5 | 65.53,60.07 67.06,60.07 LED126.A | 65.53,55.5 65.53,60.07 | 65.53,64.64 67.06,64.64 LED127.A | 65.53,60.07 65.53,64.64 | 65.53,69.22 67.06,69.22 LED128.A | 65.53,64.64 65.53,69.22 | 65.53,73.79 67.06,73.79 LED129.A | 65.53,69.22 65.53,73.79 | 65.53,73.79 65.53,78.36 67.06,78.36 LED130.A | LED121.A 66.8,37.47
  Bottom 0.61: R33.2 LED121.A
N$14  (via drill 0.9 pad 1.52)
  Top 0.406: v97.03,21.34 97.03,14.22 85.85,3.05 65.53,3.05 63.75,1.27 IC1.9
  Bottom 0.406: SV2.5 32.77,5.59 37.08,5.59 38.1,4.57 59.94,4.57 63.75,0.76 | 63.75,0.76 IC1.9 | 63.75,0.76 64.07,1.08 R41.1 | SV1.9 97.54,4.06 97.03,4.57 v97.03,21.34
N$15
  Top 0.61: 76.2,37.21 74.68,38.73 74.68,41.78 | 74.68,41.78 76.2,41.78 LED142.A | 74.68,46.35 76.2,46.35 LED143.A | 74.68,41.78 74.68,46.35 | 74.68,50.93 76.2,50.93 LED144.A | 74.68,46.35 74.68,50.93 | 74.68,55.5 76.2,55.5 LED145.A | 74.68,50.93 74.68,55.5 | 74.68,60.07 76.2,60.07 LED146.A | 74.68,55.5 74.68,60.07 | 74.68,64.64 76.2,64.64 LED147.A | 74.68,60.07 74.68,64.64 | 74.68,69.22 76.2,69.22 LED148.A | 74.68,64.64 74.68,69.22 | 74.68,73.79 76.2,73.79 LED149.A | 74.68,69.22 74.68,73.79 | 74.68,73.79 74.68,78.36 76.2,78.36 LED150.A | 76.2,37.21 75.95,37.21 | LED141.A 76.2,37.21
  Bottom 0.61: R35.2 LED141.A
N$16
  Top 0.61: 80.77,37.21 79.25,38.73 79.25,41.78 | 79.25,41.78 80.77,41.78 LED152.A | 79.25,46.35 80.77,46.35 LED153.A | 79.25,41.78 79.25,46.35 | 79.25,50.93 80.77,50.93 LED154.A | 79.25,46.35 79.25,50.93 | 79.25,55.5 80.77,55.5 LED155.A | 79.25,50.93 79.25,55.5 | 79.25,60.07 80.77,60.07 LED156.A | 79.25,55.5 79.25,60.07 | 79.25,64.64 80.77,64.64 LED157.A | 79.25,60.07 79.25,64.64 | 79.25,69.22 80.77,69.22 LED158.A | 79.25,64.64 79.25,69.22 | 79.25,73.79 80.77,73.79 LED159.A | 79.25,69.22 79.25,73.79 | 79.25,73.79 79.25,78.36 80.77,78.36 LED160.A | 80.77,37.21 80.52,37.21 | LED151.A 80.77,37.21
  Bottom 0.61: R36.2 LED151.A
N$17
  Top 0.61: 85.34,37.21 83.82,38.73 83.82,41.78 | 83.82,41.78 85.34,41.78 LED162.A | 83.82,46.35 85.34,46.35 LED163.A | 83.82,41.78 83.82,46.35 | 83.82,50.93 85.34,50.93 LED164.A | 83.82,46.35 83.82,50.93 | 83.82,55.5 85.34,55.5 LED165.A | 83.82,50.93 83.82,55.5 | 83.82,60.07 85.34,60.07 LED166.A | 83.82,55.5 83.82,60.07 | 83.82,64.64 85.34,64.64 LED167.A | 83.82,60.07 83.82,64.64 | 83.82,69.22 85.34,69.22 LED168.A | 83.82,64.64 83.82,69.22 | 83.82,73.79 85.34,73.79 LED169.A | 83.82,69.22 83.82,73.79 | 83.82,73.79 83.82,78.36 85.34,78.36 LED170.A | 85.34,37.21 85.09,37.21 | LED161.A 85.34,37.21
  Bottom 0.61: R37.2 LED161.A
N$18
  Bottom 0.406: R20.1 99.06,26.99 99.06,25.4 98.3,24.64 96.52,24.64 95.5,23.62 95.5,-1.02 93.73,-2.79 88.9,-2.79 86.61,-0.51 IC1.18
N$19
  Top 0.61: 92.96,46.35 94.49,46.35 LED183.A | 92.96,50.93 94.49,50.93 LED184.A | 92.96,46.35 92.96,50.93 | 92.96,55.5 94.49,55.5 LED185.A | 92.96,50.93 92.96,55.5 | 92.96,60.07 94.49,60.07 LED186.A | 92.96,55.5 92.96,60.07 | 92.96,64.64 94.49,64.64 LED187.A | 92.96,60.07 92.96,64.64 | 92.96,69.22 94.49,69.22 LED188.A | 92.96,64.64 92.96,69.22 | 92.96,73.79 94.49,73.79 LED189.A | 92.96,69.22 92.96,73.79 | 92.96,73.79 92.96,78.36 94.49,78.36 LED190.A | 92.96,41.78 92.96,38.99 LED181.A | 92.96,41.78 92.96,46.35 | 92.96,41.78 94.49,41.78 LED182.A
  Bottom 0.61: R39.2 LED181.A
N$20
  Bottom 0.406: IC1.19 89.41,-0.76 90.68,-2.03 92.96,-2.03 94.49,-0.51 94.49,24.38 94.55,24.95 R19.1
N$21
  Bottom 0.61: LED191.K 98.81,40.26 94.49,40.26 | 16.76,40.26 12.19,40.26 LED1.K 9.1,40.01 T21.3 | 16.76,40.26 21.34,40.26 | 21.34,40.26 26.04,40.26 | 26.04,40.26 30.61,40.26 | 30.61,40.26 35.05,40.26 | 35.05,40.26 39.75,40.26 | 39.75,40.26 44.2,40.26 | 44.2,40.26 48.77,40.26 | 48.77,40.26 53.47,40.26 | 53.47,40.26 57.91,40.26 | 57.91,40.26 62.48,40.26 | 62.48,40.26 67.06,40.26 | 67.06,40.26 71.63,40.26 | 71.63,40.26 76.33,40.26 | 76.33,40.26 80.9,40.26 | 80.9,40.26 85.34,40.26 | 85.34,40.26 89.92,40.26 | 89.92,40.26 94.49,40.26 | 16.76,40.26 LED11.K | 21.34,40.26 LED21.K | LED31.K 26.04,40.01 26.04,40.26 | LED41.K 30.61,40.01 30.61,40.26 | 35.05,40.26 LED51.K | LED61.K 39.75,40.01 39.75,40.26 | 44.2,40.26 LED71.K | 48.77,40.26 LED81.K | LED91.K 53.47,40.01 53.47,40.26 | 57.91,40.26 LED101.K | 62.48,40.26 LED111.K | 67.06,40.26 LED121.K | 71.63,40.26 LED131.K | LED141.K 76.33,40.01 76.33,40.26 | LED151.K 80.9,40.01 80.9,40.26 | 85.34,40.26 LED161.K | 89.92,40.26 LED171.K | 94.49,40.26 LED181.K
N$22
  Bottom 0.61: 16.76,44.83 12.19,44.83 LED2.K 9.1,44.58 T22.3 | 16.76,44.83 21.34,44.83 | 16.76,44.83 LED12.K | 21.34,44.83 25.91,44.83 | 21.34,44.83 LED22.K | 25.91,44.83 30.48,44.83 | 25.91,44.83 LED32.K | 30.48,44.83 35.05,44.83 | 30.48,44.83 LED42.K | 35.05,44.83 39.62,44.83 | 35.05,44.83 LED52.K | 39.62,44.83 44.2,44.83 | 39.62,44.83 LED62.K | 44.2,44.83 48.77,44.83 | 44.2,44.83 LED72.K | 48.77,44.83 53.34,44.83 | 48.77,44.83 LED82.K | 53.34,44.83 57.91,44.83 | 53.34,44.83 LED92.K | 57.91,44.83 62.48,44.83 | 57.91,44.83 LED102.K | 62.48,44.83 67.06,44.83 | 62.48,44.83 LED112.K | 67.06,44.83 71.63,44.83 | 67.06,44.83 LED122.K | 71.63,44.83 76.2,44.83 | 71.63,44.83 LED132.K | 76.2,44.83 80.77,44.83 | 76.2,44.83 LED142.K | 80.77,44.83 85.34,44.83 | 80.77,44.83 LED152.K | 85.34,44.83 89.92,44.83 | 85.34,44.83 LED162.K | 89.92,44.83 94.49,44.83 | 89.92,44.83 LED172.K | 94.49,44.83 99.06,44.83 LED192.K | 94.49,44.83 LED182.K
N$23
  Bottom 0.61: 16.76,49.4 12.19,49.4 LED3.K 9.1,49.15 T23.3 | 16.76,49.4 21.34,49.4 | 16.76,49.4 LED13.K | 21.34,49.4 25.91,49.4 | 21.34,49.4 LED23.K | 25.91,49.4 30.48,49.4 | 25.91,49.4 LED33.K | 30.48,49.4 35.05,49.4 | 30.48,49.4 LED43.K | 35.05,49.4 39.62,49.4 | 35.05,49.4 LED53.K | 39.62,49.4 44.2,49.4 | 39.62,49.4 LED63.K | 44.2,49.4 48.77,49.4 | 44.2,49.4 LED73.K | 48.77,49.4 53.34,49.4 | 48.77,49.4 LED83.K | 53.34,49.4 57.91,49.4 | 53.34,49.4 LED93.K | 57.91,49.4 62.48,49.4 | 57.91,49.4 LED103.K | 62.48,49.4 67.06,49.4 | 62.48,49.4 LED113.K | 67.06,49.4 71.63,49.4 | 67.06,49.4 LED123.K | 71.63,49.4 76.2,49.4 | 71.63,49.4 LED133.K | 76.2,49.4 80.77,49.4 | 76.2,49.4 LED143.K | 80.77,49.4 85.34,49.4 | 80.77,49.4 LED153.K | 85.34,49.4 89.92,49.4 | 85.34,49.4 LED163.K | 89.92,49.4 94.49,49.4 | 89.92,49.4 LED173.K | LED193.K 99.06,49.4 94.49,49.4 | 94.49,49.4 LED183.K
N$24
  Bottom 0.61: 16.76,53.98 12.19,53.98 LED4.K 9.1,53.72 T24.3 | 16.76,53.98 21.34,53.98 | 16.76,53.98 LED14.K | 21.34,53.98 25.91,53.98 | 21.34,53.98 LED24.K | 25.91,53.98 30.48,53.98 | 25.91,53.98 LED34.K | 30.48,53.98 35.05,53.98 | 30.48,53.98 LED44.K | 35.05,53.98 39.62,53.98 | 35.05,53.98 LED54.K | 39.62,53.98 44.2,53.98 | 39.62,53.98 LED64.K | 44.2,53.98 48.77,53.98 | 44.2,53.98 LED74.K | 48.77,53.98 53.34,53.98 | 48.77,53.98 LED84.K | 53.34,53.98 57.91,53.98 | 53.34,53.98 LED94.K | 57.91,53.98 62.48,53.98 | 57.91,53.98 LED104.K | 62.48,53.98 67.06,53.98 | 62.48,53.98 LED114.K | 67.06,53.98 71.63,53.98 | 67.06,53.98 LED124.K | 71.63,53.98 76.2,53.98 | 71.63,53.98 LED134.K | 76.2,53.98 80.77,53.98 | 76.2,53.98 LED144.K | 80.77,53.98 85.34,53.98 | 80.77,53.98 LED154.K | 85.34,53.98 89.92,53.98 | 85.34,53.98 LED164.K | 89.92,53.98 94.49,53.98 | 89.92,53.98 LED174.K | LED194.K 99.06,53.98 94.49,53.98 | 94.49,53.98 LED184.K
N$25
  Bottom 0.61: 16.76,58.55 12.19,58.55 LED5.K 9.1,58.29 T25.3 | 16.76,58.55 21.34,58.55 | 16.76,58.55 LED15.K | 21.34,58.55 25.91,58.55 | 21.34,58.55 LED25.K | 25.91,58.55 30.48,58.55 | 25.91,58.55 LED35.K | 30.48,58.55 35.05,58.55 | 30.48,58.55 LED45.K | 35.05,58.55 39.62,58.55 | 35.05,58.55 LED55.K | 39.62,58.55 44.2,58.55 | 39.62,58.55 LED65.K | 44.2,58.55 48.77,58.55 | 44.2,58.55 LED75.K | 48.77,58.55 53.34,58.55 | 48.77,58.55 LED85.K | 53.34,58.55 57.91,58.55 | 53.34,58.55 LED95.K | 57.91,58.55 62.48,58.55 | 57.91,58.55 LED105.K | 62.48,58.55 67.06,58.55 | 62.48,58.55 LED115.K | 67.06,58.55 71.63,58.55 | 67.06,58.55 LED125.K | 71.63,58.55 76.2,58.55 | 71.63,58.55 LED135.K | 76.2,58.55 80.77,58.55 | 76.2,58.55 LED145.K | 80.77,58.55 85.34,58.55 | 80.77,58.55 LED155.K | 85.34,58.55 89.92,58.55 | 85.34,58.55 LED165.K | 89.92,58.55 94.49,58.55 | 89.92,58.55 LED175.K | LED195.K 99.06,58.55 94.49,58.55 | 94.49,58.55 LED185.K
N$26
  Bottom 0.61: 16.76,63.12 12.19,63.12 LED6.K 9.1,62.87 T26.3 | 16.76,63.12 21.34,63.12 | 16.76,63.12 LED16.K | 21.34,63.12 25.91,63.12 | 21.34,63.12 LED26.K | 25.91,63.12 30.48,63.12 | 25.91,63.12 LED36.K | 30.48,63.12 35.05,63.12 | 30.48,63.12 LED46.K | 35.05,63.12 39.62,63.12 | 35.05,63.12 LED56.K | 39.62,63.12 44.2,63.12 | 39.62,63.12 LED66.K | 44.2,63.12 48.77,63.12 | 44.2,63.12 LED76.K | 48.77,63.12 53.34,63.12 | 48.77,63.12 LED86.K | 53.34,63.12 57.91,63.12 | 53.34,63.12 LED96.K | 57.91,63.12 62.48,63.12 | 57.91,63.12 LED106.K | 62.48,63.12 67.06,63.12 | 62.48,63.12 LED116.K | 67.06,63.12 71.63,63.12 | 67.06,63.12 LED126.K | 71.63,63.12 76.2,63.12 | 71.63,63.12 LED136.K | 76.2,63.12 80.77,63.12 | 76.2,63.12 LED146.K | 80.77,63.12 85.34,63.12 | 80.77,63.12 LED156.K | 85.34,63.12 89.92,63.12 | 85.34,63.12 LED166.K | 89.92,63.12 94.49,63.12 | 89.92,63.12 LED176.K | LED196.K 99.06,63.12 94.49,63.12 | 94.49,63.12 LED186.K
N$27
  Bottom 0.61: 16.76,67.69 12.19,67.69 LED7.K 9.1,67.44 T27.3 | 16.76,67.69 21.34,67.69 | 16.76,67.69 LED17.K | 21.34,67.69 25.91,67.69 | 21.34,67.69 LED27.K | 25.91,67.69 30.48,67.69 | 25.91,67.69 LED37.K | 30.48,67.69 35.05,67.69 | 30.48,67.69 LED47.K | 35.05,67.69 39.62,67.69 | 35.05,67.69 LED57.K | 39.62,67.69 44.2,67.69 | 39.62,67.69 LED67.K | 44.2,67.69 48.77,67.69 | 44.2,67.69 LED77.K | 48.77,67.69 53.34,67.69 | 48.77,67.69 LED87.K | 53.34,67.69 57.91,67.69 | 53.34,67.69 LED97.K | 57.91,67.69 62.48,67.69 | 57.91,67.69 LED107.K | 62.48,67.69 67.06,67.69 | 62.48,67.69 LED117.K | 67.06,67.69 71.63,67.69 | 67.06,67.69 LED127.K | 71.63,67.69 76.2,67.69 | 71.63,67.69 LED137.K | 76.2,67.69 80.77,67.69 | 76.2,67.69 LED147.K | 80.77,67.69 85.34,67.69 | 80.77,67.69 LED157.K | 85.34,67.69 89.92,67.69 | 85.34,67.69 LED167.K | 89.92,67.69 94.49,67.69 | 89.92,67.69 LED177.K | LED197.K 99.06,67.69 94.49,67.69 | 94.49,67.69 LED187.K
N$28
  Bottom 0.61: 16.76,72.26 12.19,72.26 LED8.K 9.1,72.01 T28.3 | 16.76,72.26 21.34,72.26 | 16.76,72.26 LED18.K | 21.34,72.26 25.91,72.26 | 21.34,72.26 LED28.K | 25.91,72.26 30.48,72.26 | 25.91,72.26 LED38.K | 30.48,72.26 35.05,72.26 | 30.48,72.26 LED48.K | 35.05,72.26 39.62,72.26 | 35.05,72.26 LED58.K | 39.62,72.26 44.2,72.26 | 39.62,72.26 LED68.K | 44.2,72.26 48.77,72.26 | 44.2,72.26 LED78.K | 48.77,72.26 53.34,72.26 | 48.77,72.26 LED88.K | 53.34,72.26 57.91,72.26 | 53.34,72.26 LED98.K | 57.91,72.26 62.48,72.26 | 57.91,72.26 LED108.K | 62.48,72.26 67.06,72.26 | 62.48,72.26 LED118.K | 67.06,72.26 71.63,72.26 | 67.06,72.26 LED128.K | 71.63,72.26 76.2,72.26 | 71.63,72.26 LED138.K | 76.2,72.26 80.77,72.26 | 76.2,72.26 LED148.K | 80.77,72.26 85.34,72.26 | 80.77,72.26 LED158.K | 85.34,72.26 89.92,72.26 | 85.34,72.26 LED168.K | 89.92,72.26 94.49,72.26 | 89.92,72.26 LED178.K | LED198.K 99.06,72.26 94.49,72.26 | 94.49,72.26 LED188.K
N$29
  Bottom 0.61: 16.76,76.83 12.19,76.83 LED9.K 9.1,76.58 T29.3 | 16.76,76.83 21.34,76.83 | 16.76,76.83 LED19.K | 21.34,76.83 25.91,76.83 | 21.34,76.83 LED29.K | 25.91,76.83 30.48,76.83 | 25.91,76.83 LED39.K | 30.48,76.83 35.05,76.83 | 30.48,76.83 LED49.K | 35.05,76.83 39.62,76.83 | 35.05,76.83 LED59.K | 39.62,76.83 44.2,76.83 | 39.62,76.83 LED69.K | 44.2,76.83 48.77,76.83 | 44.2,76.83 LED79.K | 48.77,76.83 53.34,76.83 | 48.77,76.83 LED89.K | 53.34,76.83 57.91,76.83 | 53.34,76.83 LED99.K | 57.91,76.83 62.48,76.83 | 57.91,76.83 LED109.K | 62.48,76.83 67.06,76.83 | 62.48,76.83 LED119.K | 67.06,76.83 71.63,76.83 | 67.06,76.83 LED129.K | 71.63,76.83 76.2,76.83 | 71.63,76.83 LED139.K | 76.2,76.83 80.77,76.83 | 76.2,76.83 LED149.K | 80.77,76.83 85.34,76.83 | 80.77,76.83 LED159.K | 85.34,76.83 89.92,76.83 | 85.34,76.83 LED169.K | 89.92,76.83 94.49,76.83 | 89.92,76.83 LED179.K | LED199.K 99.06,76.83 94.49,76.83 | 94.49,76.83 LED189.K
N$30
  Bottom 0.61: LED200.K 99.06,81.41 94.49,81.41 | 16.76,81.41 12.19,81.41 LED10.K 9.1,81.15 T30.3 | 16.76,81.41 21.34,81.41 | 21.34,81.41 25.91,81.41 | 25.91,81.41 30.48,81.41 | 30.48,81.41 35.05,81.41 | 35.05,81.41 39.62,81.41 | 39.62,81.41 44.2,81.41 | 44.2,81.41 48.77,81.41 | 53.34,81.41 57.91,81.41 | 57.91,81.41 62.48,81.41 | 62.48,81.41 67.06,81.41 | 67.06,81.41 71.63,81.41 | 71.63,81.41 76.2,81.41 | 76.2,81.41 80.77,81.41 | 80.77,81.41 85.34,81.41 | 85.34,81.41 89.92,81.41 | 89.92,81.41 94.49,81.41 | 16.76,81.41 LED20.K | 21.34,81.41 LED30.K | 25.91,81.41 LED40.K | 30.48,81.41 LED50.K | 35.05,81.41 LED60.K | 39.62,81.41 LED70.K | 44.2,81.41 LED80.K | 48.77,81.41 LED90.K | 48.77,81.41 53.34,81.41 | 53.34,81.41 LED100.K | 57.91,81.41 LED110.K | 62.48,81.41 LED120.K | 67.06,81.41 LED130.K | 71.63,81.41 LED140.K | 76.2,81.41 LED150.K | 80.77,81.41 LED160.K | 85.34,81.41 LED170.K | 89.92,81.41 LED180.K | 94.49,81.41 LED190.K
N$31
  Bottom 0.406: T1.B 10.35,28.75 R1.2
N$32
  Bottom 0.406: T2.B 14.93,28.75 R2.2
N$33
  Bottom 0.406: T3.B 19.5,28.75 R3.2
N$34
  Bottom 0.406: T4.B 24.07,28.75 R4.2
N$35
  Bottom 0.406: T5.B 28.64,28.75 R5.2
N$36
  Bottom 0.406: T6.B 33.21,28.75 R6.2
N$37
  Bottom 0.406: T7.B 37.78,28.75 R7.2
N$38
  Bottom 0.406: T8.B 42.36,28.75 R8.2
N$39
  Bottom 0.406: T9.B 46.93,28.75 R9.2
N$40
  Bottom 0.406: T10.B 51.5,28.75 R10.2
N$41
  Bottom 0.406: T11.B 56.07,28.75 R11.2
N$42
  Bottom 0.406: T12.B 60.65,28.75 R12.2
N$43
  Bottom 0.406: T13.B 65.22,28.75 R13.2
N$44
  Bottom 0.406: T14.B 69.79,28.75 R14.2
N$45
  Bottom 0.406: T15.B 74.36,28.75 R15.2
N$46
  Bottom 0.406: T16.B 78.93,28.75 R16.2
N$47
  Bottom 0.406: T17.B 83.5,28.75 R17.2
N$48
  Bottom 0.406: T18.B 88.08,28.75 R18.2
N$49
  Bottom 0.406: T19.B 92.65,28.75 R19.2
N$50
  Bottom 0.406: T20.B 97.22,28.75 R20.2
N$51
  Bottom 0.406: T1.C 12.19,30.06 R21.1
N$52
  Bottom 0.406: R26.1 35.14,32.53 T6.C
N$53
  Bottom 0.406: T2.C 16.76,30.06 R22.1
N$54
  Bottom 0.406: R23.1 21.42,32.53 T3.C
N$55
  Bottom 0.406: T4.C 25.91,30.06 R24.1
N$56
  Bottom 0.406: R25.1 30.56,32.53 T5.C
N$57
  Bottom 0.406: R27.1 39.71,32.53 T7.C
N$58
  Bottom 0.406: T8.C 44.2,30.06 R28.1
N$59
  Bottom 0.406: T9.C 48.77,30.06 R29.1
N$60
  Bottom 0.406: R30.1 53.42,32.53 T10.C
N$61
  Bottom 0.406: T11.C 57.91,30.06 R31.1
N$62
  Bottom 0.406: T12.C 62.48,30.06 R32.1
N$63
  Bottom 0.406: T13.C 67.06,30.06 R33.1
N$64
  Bottom 0.406: T14.C 71.63,30.06 R34.1
N$65
  Bottom 0.406: T15.C 76.2,30.06 R35.1
N$66
  Bottom 0.406: T16.C 80.77,30.06 R36.1
N$67
  Bottom 0.406: T17.C 85.34,30.06 R37.1
N$68
  Bottom 0.406: R38.1 90,32.53 T18.C
N$69
  Bottom 0.406: R39.1 94.57,32.53 T19.C
N$70
  Bottom 0.406: R40.1 99.14,32.53 T20.C
N$71
  Top 0.61: 97.54,41.78 97.54,38.99 LED191.A | 97.54,41.78 97.54,46.35 | 97.54,46.35 97.54,50.93 | 97.54,50.93 97.54,55.5 | 97.54,55.5 97.54,60.07 | 97.54,60.07 97.54,64.64 | 97.54,64.64 97.54,69.22 | 97.54,69.22 97.54,73.79 | 97.54,73.79 97.54,78.36 99.06,78.36 LED200.A | 97.54,73.79 99.06,73.79 LED199.A | 97.54,69.22 99.06,69.22 LED198.A | 97.54,64.64 99.06,64.64 LED197.A | 97.54,60.07 99.06,60.07 LED196.A | LED195.A 99.06,55.5 97.54,55.5 | LED194.A 99.06,50.93 97.54,50.93 | LED193.A 99.06,46.35 97.54,46.35 | LED192.A 99.06,41.78 97.54,41.78
  Bottom 0.61: R40.2 LED191.A
N$72
  Top 0.61: 88.39,46.35 89.92,46.35 LED173.A | 88.39,50.93 89.92,50.93 LED174.A | 88.39,46.35 88.39,50.93 | 88.39,55.5 89.92,55.5 LED175.A | 88.39,50.93 88.39,55.5 | 88.39,60.07 89.92,60.07 LED176.A | 88.39,55.5 88.39,60.07 | 88.39,64.64 89.92,64.64 LED177.A | 88.39,60.07 88.39,64.64 | 88.39,69.22 89.92,69.22 LED178.A | 88.39,64.64 88.39,69.22 | 88.39,73.79 89.92,73.79 LED179.A | 88.39,69.22 88.39,73.79 | 88.39,73.79 88.39,78.36 89.92,78.36 LED180.A | 88.39,41.78 88.39,38.99 LED171.A | 88.39,41.78 88.39,46.35 | 88.39,41.78 89.92,41.78 LED172.A
  Bottom 0.61: R38.2 LED171.A
N$73
  Top 0.61: 71.63,37.21 70.1,38.73 70.1,41.78 | 70.1,41.78 71.63,41.78 LED132.A | 70.1,46.35 71.63,46.35 LED133.A | 70.1,41.78 70.1,46.35 | 70.1,50.93 71.63,50.93 LED134.A | 70.1,46.35 70.1,50.93 | 70.1,55.5 71.63,55.5 LED135.A | 70.1,50.93 70.1,55.5 | 70.1,60.07 71.63,60.07 LED136.A | 70.1,55.5 70.1,60.07 | 70.1,64.64 71.63,64.64 LED137.A | 70.1,60.07 70.1,64.64 | 70.1,69.22 71.63,69.22 LED138.A | 70.1,64.64 70.1,69.22 | 70.1,73.79 71.63,73.79 LED139.A | 70.1,69.22 70.1,73.79 | 70.1,73.79 70.1,78.36 71.63,78.36 LED140.A | 71.63,37.21 71.37,37.21 | LED131.A 71.63,37.21
  Bottom 0.61: R34.2 LED131.A
N$74  (via drill 0.9 pad 1.52)
  Top 0.406: v-1.02,49.78 2.54,49.78 7.62,44.7 7.62,35.05 32,10.67 55.37,10.67 56.39,9.65 56.39,0.25 IC1.6
  Bottom 0.406: SV2.4 35.81,-3.05 54.36,-3.05 56.13,-1.27 IC1.6 | R49.1 -3.05,70.1 -3.05,49.78 | -3.05,49.78 -3.05,47.24 R44.1 | v-1.02,49.78 -3.05,49.78
N$75  (via drill 0.9 pad 1.52)
  Top 0.406: IC1.7 58.67,10.92 57.91,11.68 32.51,11.68 8.64,35.56 8.64,45.72 0,54.36 v-0.51,54.36
  Bottom 0.406: SV2.1 35.31,2.54 56.9,2.54 58.67,0.76 IC1.7 | R48.1 -2.03,65.53 -2.03,54.36 | R45.1 -2.03,51.82 -2.03,53.85 -2.03,54.36 | v-0.51,54.36 -2.03,54.36
N$76
  Bottom 0.406: IC1.20 93.47,1.78 93.47,21.84 89.98,24.83 R18.1
N$77
  Bottom 0.406: R17.1 85.34,26.99 85.34,26.42 91.69,20.07 IC1.21
N$78  (via drill 0.9 pad 1.52)
  Top 0.406: IC1.8 61.21,10.92 59.44,12.7 33.02,12.7 9.65,36.07 9.65,48.77 v0,58.42
  Bottom 0.406: SV2.3 34.29,4.57 36.58,4.57 37.59,3.56 58.93,3.56 61.21,1.27 IC1.8 | R47.1 -1.02,60.96 -1.02,58.42 | -1.02,58.42 -1.02,56.39 R46.1 | v0,58.42 -1.02,58.42
N$79
  Bottom 0.406: R16.1 89.15,18.73 IC1.22
N$80
  Bottom 0.406: IC1.12 71.63,0.25 71.63,2.03 72.9,3.3 Q1.2 72.9,8.82 C1.1
N$81
  Bottom 0.406: IC1.13 74.17,0.25 74.17,1.52 75.69,3.05 81.28,3.05 82.55,4.32 Q1.1 82.55,8.32 C2.1
N$82
  Bottom 0.406: SV1.4 104.65,8.38 104.65,2.03 96.77,-5.84 82.04,-5.84 76.45,-0.25 IC1.14
N$83
  Bottom 0.406: SV1.6 103.63,6.86 103.63,2.29 96.27,-5.08 84.07,-5.08 IC1.15
N$84
  Bottom 0.406: SV1.8 102.87,5.08 102.87,3.05 95.25,-4.32 85.6,-4.32 81.53,-0.25 IC1.16
N$85
  Bottom 0.406: SV1.10 101.35,3.3 94.49,-3.56 87.12,-3.56 84.07,-0.51 IC1.17
N$86
  Bottom 0.406: R15.1 86.61,16.7 IC1.23
N$87
  Bottom 0.406: R14.1 73.59,25.15 74.42,25.15 84.07,15.49 IC1.24
N$88
  Bottom 0.406: R13.1 69.28,24.89 72.14,24.89 81.53,15.49 IC1.25
N$89
  Bottom 0.406: R12.1 65.72,23.88 71.63,23.88 78.99,16.51 IC1.26
N$90
  Bottom 0.406: R11.1 62.16,22.86 71.12,22.86 76.45,17.53 IC1.27
N$91
  Bottom 0.406: R10.1 58.61,21.84 70.61,21.84 73.91,18.54 IC1.28
N$92
  Bottom 0.61: IC3.1 17.02,0.25 C3.+ 21.57,0.49 C6.1
  Bottom 1.016: D3.C 12.45,1.02 IC3.1
N$93
  Bottom 1.016: U$1.I 3.56,10.67 10.16,10.67 12.19,8.64 D3.A
N$94
  Bottom 0.406: R42.2 3.01,38.17 T21.1
N$95
  Bottom 0.406: R9.1 55.05,20.83 70.1,20.83 71.37,19.56 IC1.29
N$96
  Bottom 0.406: R8.1 46.42,24.89 48.77,24.89 53.85,19.81 59.69,19.81 61.21,18.29 IC1.33
N$97
  Bottom 0.406: R7.1 42.86,23.88 48.26,23.88 53.34,18.8 57.66,18.8 58.67,17.78 IC1.34
N$98
  Bottom 0.406: R6.1 39.3,22.86 47.75,22.86 52.83,17.78 55.88,17.78 56.13,17.53 IC1.35
N$99
  Bottom 0.406: R5.1 35.75,21.84 47.24,21.84 53.59,15.49 IC1.36
N$100
  Bottom 0.406: R4.1 32.19,20.83 46.74,20.83 51.05,16.51 IC1.37
N$101
  Bottom 0.406: R3.1 28.64,19.81 46.23,19.81 48.51,17.53 IC1.38
N$102
  Bottom 0.406: R2.1 18.48,25.4 21.34,25.4 27.94,18.8 43.69,18.8 45.97,16.51 IC1.39
N$103
  Bottom 0.406: R1.1 14.92,24.38 20.83,24.38 27.43,17.78 41.15,17.78 43.43,15.49 IC1.40
N$104
  Bottom 0.406: R43.2 6.01,42.67 T22.1
N$105
  Bottom 0.406: R44.2 6.01,47.24 T23.1
N$106
  Bottom 0.406: R45.2 6.01,51.82 T24.1
N$107
  Bottom 0.406: T25.1 2.95,56.45 R46.2
N$108
  Bottom 0.406: R47.2 6.01,60.96 T26.1
N$109
  Bottom 0.406: T27.1 2.95,65.6 R48.2
N$110
  Bottom 0.406: T28.1 2.95,70.17 R49.2
N$111
  Bottom 0.406: T29.1 2.95,74.74 R50.2
N$112
  Bottom 0.406: T30.1 2.95,79.31 R51.2
N$113
  Bottom 0.406: R52.2 3.13,35.03 T31.1
N$114
  Bottom 0.406: R53.2 3.13,28.43 T32.1
N$115  (via drill 0.9 pad 1.52)
  Top 0.406: v11.68,24.38 13.72,24.38 30.48,7.62 46.74,7.62 48.51,5.84 IC1.3
  Bottom 0.406: R52.1 8.13,32.92 8.13,25.91 9.65,24.38 v11.68,24.38
N$116  (via drill 0.9 pad 1.52)
  Top 0.406: v-1.52,45.21 5.08,45.21 6.6,43.69 6.6,34.54 31.5,9.65 52.32,9.65 53.59,8.38 IC1.5
  Bottom 0.406: R50.1 -4.06,74.68 -4.06,45.21 | -4.06,45.21 -4.06,42.67 R43.1 | v-1.52,45.21 -4.06,45.21
N$117  (via drill 0.9 pad 1.52)
  Top 0.406: v-2.03,40.64 4.57,40.64 5.59,39.62 5.59,34.04 30.99,8.64 49.28,8.64 51.05,6.86 IC1.4
  Bottom 0.406: -5.08,40.64 -5.08,38.1 R42.1 | -5.08,40.64 v-2.03,40.64 | -5.08,40.64 -5.08,75.18 -1.02,79.25 R51.1
N$118
  Bottom 0.406: T25.2 1.52,58.35 1.52,53.78 | 1.52,40.13 1.52,44.64 | 1.52,40.13 6.01,40.13 T21.2 | 1.52,44.64 T22.2 | 1.52,44.64 1.52,49.21 | 1.52,49.21 T23.2 | 1.52,49.21 1.52,53.78 | 1.52,53.78 T24.2 | T31.3 1.52,32.6 1.52,40.13
N$119
  Bottom 0.406: 1.52,81.21 T30.2 | 1.52,67.5 1.52,62.99 6.01,62.99 T26.2 | 1.52,67.5 T27.2 | 1.52,72.07 1.52,67.5 | 1.52,72.07 T28.2 | 1.52,76.64 1.52,72.07 | 1.52,76.64 T29.2 | 1.52,81.21 1.52,76.64 | T32.3 -6.1,32.43 -6.1,76.2 -1.08,81.21 1.52,81.21
N$120  (via drill 0.9 pad 1.52)
  Top 0.406: v13.21,22.35 14.22,22.35 29.97,6.6 44.7,6.6 45.97,5.33 IC1.2
  Bottom 0.406: R53.1 7.11,27.33 7.11,25.4 10.16,22.35 v13.21,22.35
N$121
  Top 0.406: LED201.A 14.99,13.21 R54.2
N$122
  Top 0.406: R54.1 21.84,13.21 29.46,5.59 42.16,5.59 43.43,4.32 IC1.1

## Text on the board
Top: 2012-10-29 | 10x20 graphical LED display | Supply | ICP
Bottom: 2012-10-29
